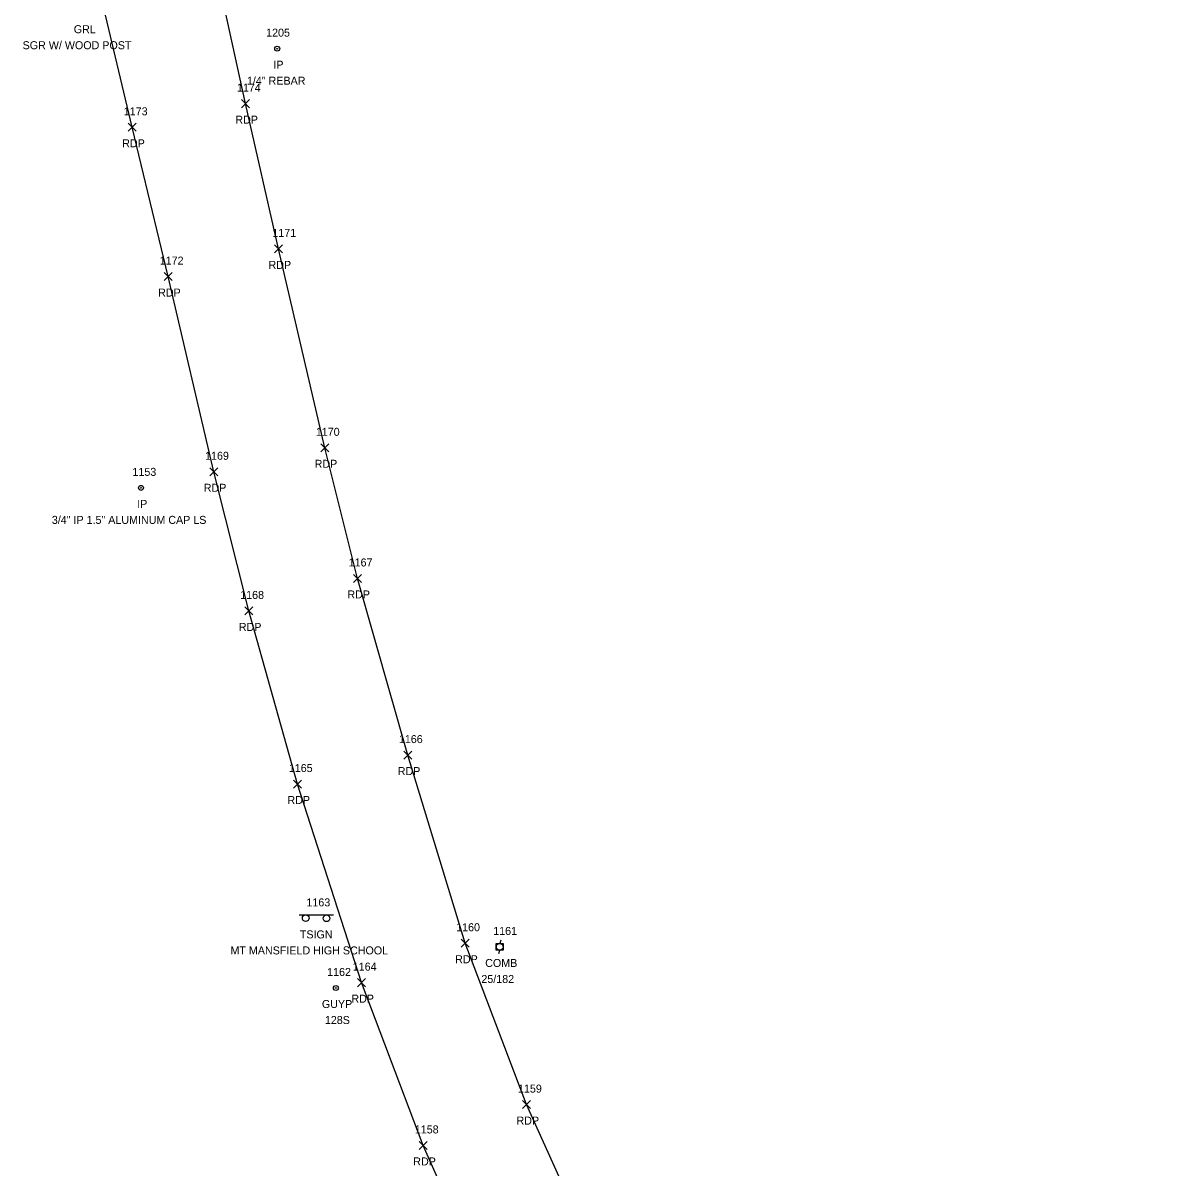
# Model space of a CAD drawing. Extents: x 1503463 to 1505240, y 712171 to 717196.
# Drawn here: x 1504601.6 to 1504890.4, y 714311.7 to 714597.7 of the extents above; entities that cross this region are included whole.
import ezdxf

# ---------------------------------------------------------------- set-up
doc = ezdxf.new("R2010")
doc.units = 0
for name, color, linetype in [('M_A', 7, 'Continuous'), ('M_C', 7, 'Continuous'), ('M_I', 7, 'Continuous'), ('MPIR', 7, 'Continuous'), ('P_A', 7, 'Continuous'), ('P_I', 7, 'Continuous'), ('P_TIC', 7, 'Continuous'), ('PET', 7, 'Continuous'), ('R_A', 7, 'Continuous'), ('R_C', 7, 'Continuous'), ('S_A', 7, 'Continuous'), ('S_C', 7, 'Continuous'), ('S_I', 7, 'Continuous'), ('SSGN', 7, 'Continuous'), ('U_A', 7, 'Continuous'), ('U_C', 7, 'Continuous'), ('U_I', 7, 'Continuous'), ('UP', 7, 'Continuous'), ('UPGW', 7, 'Continuous')]:
    doc.layers.add(name, color=color, linetype=linetype)

msp = doc.modelspace()

# ---------------------------------------------------------------- linework, layer by layer
at = {"layer": 'MPIR'}
for centre, radius in [((1504665.08, 714591.34), 0.625), ((1504665.08, 714591.34), 0.0833), ((1504631.04, 714481.6), 0.625), ((1504631.04, 714481.6), 0.0833)]:
    msp.add_circle(centre, radius, dxfattribs=at)
at = {"layer": 'P_TIC'}
for points in [[(1504656.14, 714576.6), (1504658.14, 714578.6)], [(1504658.14, 714576.6), (1504656.14, 714578.6)], [(1504627.86, 714570.69), (1504629.86, 714572.69)], [(1504629.86, 714570.69), (1504627.86, 714572.69)], [(1504664.42, 714540.32), (1504666.42, 714542.32)], [(1504666.42, 714540.32), (1504664.42, 714542.32)], [(1504636.84, 714533.39), (1504638.84, 714535.39)], [(1504638.84, 714533.39), (1504636.84, 714535.39)], [(1504675.94, 714490.61), (1504677.94, 714492.61)], [(1504677.94, 714490.61), (1504675.94, 714492.61)], [(1504648.24, 714484.62), (1504650.24, 714486.62)], [(1504650.24, 714484.62), (1504648.24, 714486.62)], [(1504684.11, 714457.97), (1504686.11, 714459.97)], [(1504686.11, 714457.97), (1504684.11, 714459.97)], [(1504657, 714449.85), (1504659, 714451.85)], [(1504659, 714449.85), (1504657, 714451.85)], [(1504696.71, 714413.83), (1504698.71, 714415.83)], [(1504698.71, 714413.83), (1504696.71, 714415.83)], [(1504669.15, 714406.6), (1504671.15, 714408.6)], [(1504671.15, 714406.6), (1504669.15, 714408.6)], [(1504711.05, 714366.82), (1504713.05, 714368.82)], [(1504713.05, 714366.82), (1504711.05, 714368.82)], [(1504685.12, 714356.97), (1504687.12, 714358.97)], [(1504687.12, 714356.97), (1504685.12, 714358.97)], [(1504726.38, 714326.5), (1504728.38, 714328.5)], [(1504728.38, 714326.5), (1504726.38, 714328.5)], [(1504700.58, 714316.3), (1504702.58, 714318.3)], [(1504702.58, 714316.3), (1504700.58, 714318.3)]]:
    msp.add_lwpolyline(points, dxfattribs=at)
at = {"layer": 'PET'}
for points in [[(1505179.12, 714062.13), (1505162.73, 714064.23), (1505117.1, 714071.16), (1505063.73, 714078.62), (1505006.07, 714088.04), (1504974.7, 714091.87), (1504950.76, 714094.03), (1504913.58, 714099.65), (1504891.67, 714105.18), (1504874.38, 714111.13), (1504858.75, 714121.03), (1504839.76, 714141.64), (1504813.09, 714174.5), (1504792.31, 714203.38), (1504770.85, 714238.46), (1504747.85, 714282.15), (1504727.38, 714327.5), (1504712.05, 714367.82), (1504697.71, 714414.83), (1504685.11, 714458.97), (1504676.94, 714491.61), (1504665.42, 714541.32), (1504657.14, 714577.6), (1504649.31, 714613.48)], [(1505055.48, 713804.69), (1505035.67, 713846.75), (1505012.25, 713888.12), (1504984.81, 713930.29), (1504955.82, 713968.98), (1504925.45, 714007.09), (1504902.19, 714033.47), (1504875.2, 714061.56), (1504841.23, 714097.76), (1504824.92, 714116.29), (1504805.14, 714139.73), (1504789.93, 714158.37), (1504770.9, 714185.14), (1504747.1, 714223.61), (1504721.17, 714273.06), (1504701.58, 714317.3), (1504686.12, 714357.97), (1504670.15, 714407.6), (1504658, 714450.85), (1504649.24, 714485.62), (1504637.84, 714534.39), (1504628.86, 714571.69), (1504621.33, 714603.22)]]:
    msp.add_lwpolyline(points, dxfattribs=at)
at = {"layer": 'SSGN'}
for p, q in [((1504670.53, 714374.95), (1504679.13, 714374.95)), ((1504674.55, 714374.05), (1504674.55, 714374.05))]:
    msp.add_line(p, q, dxfattribs=at)
for centre in [(1504672.19, 714374.12), (1504677.41, 714374.05)]:
    msp.add_circle(centre, 0.833, dxfattribs=at)
at = {"layer": 'UP'}
for p, q in [((1504720.91, 714368.56), (1504720.66, 714367.72)), ((1504719.82, 714366.06), (1504719.82, 714367.72)), ((1504719.82, 714367.72), (1504721.49, 714367.72)), ((1504721.49, 714366.06), (1504719.82, 714366.06)), ((1504720.41, 714365.22), (1504720.66, 714366.06)), ((1504720.66, 714366.89), (1504720.66, 714366.89)), ((1504721.49, 714367.72), (1504721.49, 714366.06))]:
    msp.add_line(p, q, dxfattribs=at)
msp.add_circle((1504720.66, 714366.89), 0.833, dxfattribs=at)
at = {"layer": 'UPGW'}
for radius in [0.625, 0.0833]:
    msp.add_circle((1504679.73, 714356.64), radius, dxfattribs=at)

# ---------------------------------------------------------------- texts
at = {"layer": 'M_A'}
for p in [(1504664.12, 714586.34), (1504630.09, 714476.6)]:
    msp.add_text('IP', height=2, dxfattribs=at).set_placement(p)
at = {"layer": 'M_C'}
for s, p in [('1/4" REBAR', (1504657.51, 714582.34)), ('3/4" IP 1.5" ALUMINUM CAP LS', (1504608.77, 714472.6))]:
    msp.add_text(s, height=2, dxfattribs=at).set_placement(p)
at = {"layer": 'M_I'}
for s, p in [('1205', (1504662.31, 714594.34)), ('1153', (1504628.91, 714484.6))]:
    msp.add_text(s, height=2, dxfattribs=at).set_placement(p)
at = {"layer": 'P_A'}
for p in [(1504654.62, 714572.6), (1504626.35, 714566.69), (1504662.91, 714536.32), (1504635.33, 714529.39), (1504674.43, 714486.61), (1504646.73, 714480.62), (1504682.6, 714453.97), (1504655.49, 714445.85), (1504695.2, 714409.83), (1504667.64, 714402.6), (1504709.54, 714362.82), (1504683.61, 714352.97), (1504724.87, 714322.5), (1504699.07, 714312.3)]:
    msp.add_text('RDP', height=2, dxfattribs=at).set_placement(p)
at = {"layer": 'P_I'}
for s, p in [('1174', (1504655.01, 714580.6)), ('1173', (1504626.74, 714574.69)), ('1171', (1504663.87, 714544.32)), ('1172', (1504635.72, 714537.39)), ('1170', (1504674.73, 714494.61)), ('1169', (1504647.06, 714488.62)), ('1167', (1504682.93, 714461.97)), ('1168', (1504655.83, 714453.85)), ('1166', (1504695.48, 714417.83)), ('1165', (1504667.98, 714410.6)), ('1160', (1504709.79, 714370.82)), ('1164', (1504683.95, 714360.97)), ('1159', (1504725.24, 714330.5)), ('1158', (1504699.46, 714320.3))]:
    msp.add_text(s, height=2, dxfattribs=at).set_placement(p)
at = {"layer": 'R_A'}
msp.add_text('GRL', height=2, dxfattribs=at).set_placement((1504614.25, 714595.2))
at = {"layer": 'R_C'}
msp.add_text('SGR W/ WOOD POST', height=2, dxfattribs=at).set_placement((1504601.47, 714591.2))
at = {"layer": 'S_A'}
msp.add_text('TSIGN', height=2, dxfattribs=at).set_placement((1504670.73, 714369.03))
at = {"layer": 'S_C'}
msp.add_text('MT MANSFIELD HIGH SCHOOL', height=2, dxfattribs=at).set_placement((1504653.4, 714365.03))
at = {"layer": 'S_I'}
msp.add_text('1163', height=2, dxfattribs=at).set_placement((1504672.38, 714377.03))
at = {"layer": 'U_A'}
for s, p in [('COMB', (1504717.04, 714361.89)), ('GUYP', (1504676.24, 714351.64))]:
    msp.add_text(s, height=2, dxfattribs=at).set_placement(p)
at = {"layer": 'U_C'}
for s, p in [('25/182', (1504716.09, 714357.89)), ('128S', (1504676.99, 714347.64))]:
    msp.add_text(s, height=2, dxfattribs=at).set_placement(p)
at = {"layer": 'U_I'}
for s, p in [('1161', (1504719.05, 714369.89)), ('1162', (1504677.55, 714359.64))]:
    msp.add_text(s, height=2, dxfattribs=at).set_placement(p)

doc.saveas('drawing.dxf')
